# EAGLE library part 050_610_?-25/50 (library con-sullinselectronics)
.050 DIP EDGE CARD CONNECTOR .050 [1.27mm] CONTACT CENTERS .610" INSULATEOR HEIGHT Source: .050 DIP EDGE CARD.pdf
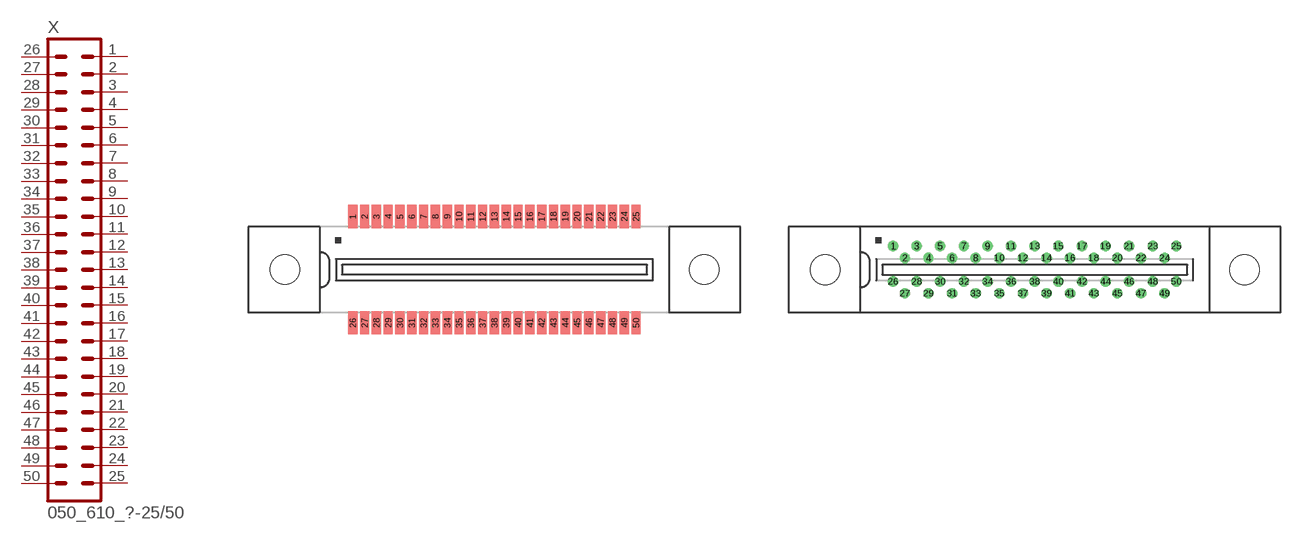
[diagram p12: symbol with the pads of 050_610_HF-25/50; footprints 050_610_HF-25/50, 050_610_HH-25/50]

Designator prefix X

## 050_610_HF-25/50 (OC_FARNELL: unknown; OC_NEWARK: unknown)  [050_610_HF-25/50]
1  1  pas
2  2  pas
3  3  pas
4  4  pas
5  5  pas
6  6  pas
7  7  pas
8  8  pas
9  9  pas
10  10  pas
11  11  pas
12  12  pas
13  13  pas
14  14  pas
15  15  pas
16  16  pas
17  17  pas
18  18  pas
19  19  pas
20  20  pas
21  21  pas
22  22  pas
23  23  pas
24  24  pas
25  25  pas
26  26  pas
27  27  pas
28  28  pas
29  29  pas
30  30  pas
31  31  pas
32  32  pas
33  33  pas
34  34  pas
35  35  pas
36  36  pas
37  37  pas
38  38  pas
39  39  pas
40  40  pas
41  41  pas
42  42  pas
43  43  pas
44  44  pas
45  45  pas
46  46  pas
47  47  pas
48  48  pas
49  49  pas
50  50  pas

## 050_610_HH-25/50 (OC_FARNELL: unknown; OC_NEWARK: unknown)  [050_610_HH-25/50]
Pads as for 050_610_HF-25/50

## Footprint 050_610_HF-25/50 (pad centres in mm)
.050 DIP EDGE CARD CONNECTOR SURFACE MOUNT .050 [1.27mm] CONTACT CENTERS .610" INSULATEOR HEIGHT Source: .050 DIP EDGE CARD.pdf
smd 1 x 2.5: 1 -15.24,5.715; 2 -13.97,5.715; 3 -12.7,5.715; 4 -11.43,5.715; 5 -10.16,5.715; 6 -8.89,5.715; 7 -7.62,5.715; 8 -6.35,5.715; 9 -5.08,5.715; 10 -3.81,5.715; 11 -2.54,5.715; 12 -1.27,5.715; 13 0,5.715; 14 1.27,5.715; 15 2.54,5.715; 16 3.81,5.715; 17 5.08,5.715; 18 6.35,5.715; 19 7.62,5.715; 20 8.89,5.715; 21 10.16,5.715; 22 11.43,5.715; 23 12.7,5.715; 24 13.97,5.715; 25 15.24,5.715; 26 -15.24,-5.715; 27 -13.97,-5.715; 28 -12.7,-5.715; 29 -11.43,-5.715; 30 -10.16,-5.715; 31 -8.89,-5.715; 32 -7.62,-5.715; 33 -6.35,-5.715; 34 -5.08,-5.715; 35 -3.81,-5.715; 36 -2.54,-5.715; 37 -1.27,-5.715; 38 0,-5.715; 39 1.27,-5.715; 40 2.54,-5.715; 41 3.81,-5.715; 42 5.08,-5.715; 43 6.35,-5.715; 44 7.62,-5.715; 45 8.89,-5.715; 46 10.16,-5.715; 47 11.43,-5.715; 48 12.7,-5.715; 49 13.97,-5.715; 50 15.24,-5.715
hole 3.18 at -22.555,0
hole 3.18 at 22.555,0

## Footprint 050_610_HH-25/50 (pad centres in mm)
.050 DIP EDGE CARD CONNECTOR STAGGERED DIP SOLDER .050 [1.27mm] CONTACT CENTERS .610" INSULATEOR HEIGHT Source: .050 DIP EDGE CARD.pdf
drill 0.6 pad 1 round: 1 -15.24,2.54; 2 -13.97,1.27; 3 -12.7,2.54; 4 -11.43,1.27; 5 -10.16,2.54; 6 -8.89,1.27; 7 -7.62,2.54; 8 -6.35,1.27; 9 -5.08,2.54; 10 -3.81,1.27; 11 -2.54,2.54; 12 -1.27,1.27; 13 0,2.54; 14 1.27,1.27; 15 2.54,2.54; 16 3.81,1.27; 17 5.08,2.54; 18 6.35,1.27; 19 7.62,2.54; 20 8.89,1.27; 21 10.16,2.54; 22 11.43,1.27; 23 12.7,2.54; 24 13.97,1.27; 25 15.24,2.54; 26 -15.24,-1.27; 27 -13.97,-2.54; 28 -12.7,-1.27; 29 -11.43,-2.54; 30 -10.16,-1.27; 31 -8.89,-2.54; 32 -7.62,-1.27; 33 -6.35,-2.54; 34 -5.08,-1.27; 35 -3.81,-2.54; 36 -2.54,-1.27; 37 -1.27,-2.54; 38 0,-1.27; 39 1.27,-2.54; 40 2.54,-1.27; 41 3.81,-2.54; 42 5.08,-1.27; 43 6.35,-2.54; 44 7.62,-1.27; 45 8.89,-2.54; 46 10.16,-1.27; 47 11.43,-2.54; 48 12.7,-1.27; 49 13.97,-2.54; 50 15.24,-1.27
hole 3.18 at -22.555,0
hole 3.18 at 22.555,0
